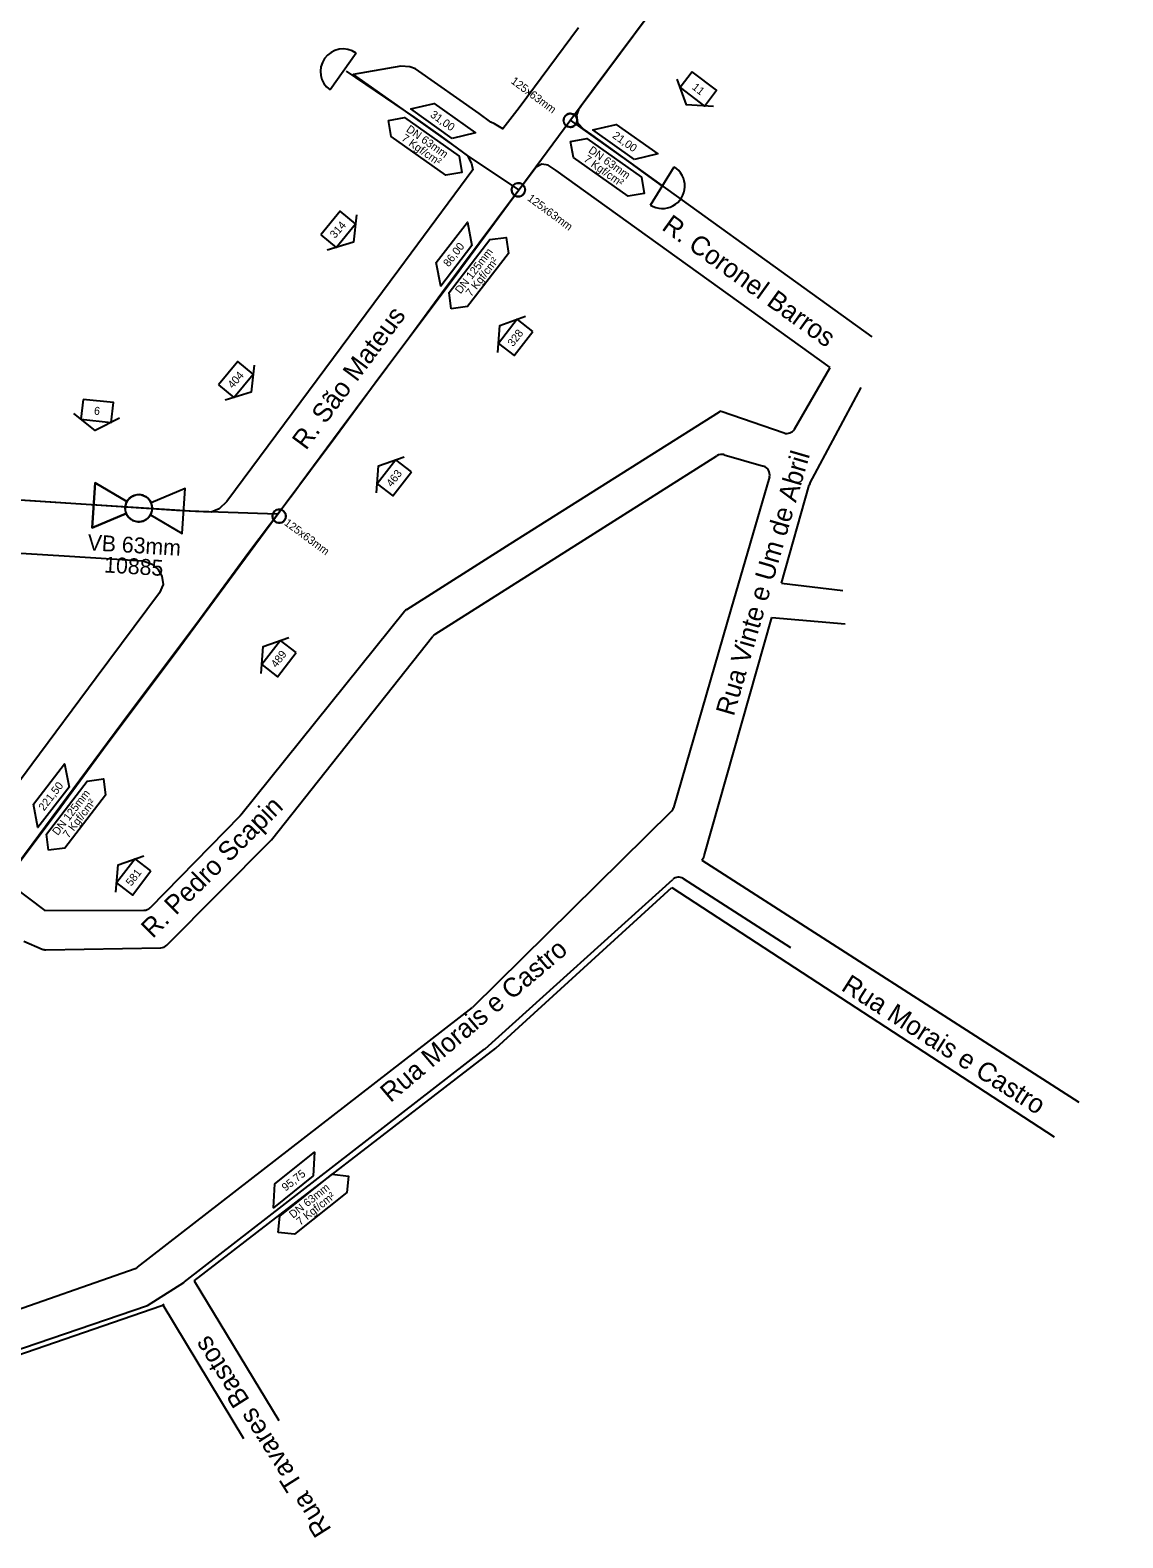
# Model space of a CAD drawing. Extents: x 656692 to 673945, y 7585994 to 7599066.
# Drawn here: x 669719 to 670131, y 7591270 to 7591839 of the extents above; entities that cross this region are included whole.
import ezdxf

# ---------------------------------------------------------------- set-up
doc = ezdxf.new("R2010")
doc.units = 0
for name, color, linetype in [('FORMATO', 7, 'Continuous'), ('LOGRADOURO', 7, 'Continuous'), ('LOGRADOURO_TEXTO', 7, 'Continuous'), ('NUM_REF', 7, 'Continuous'), ('SIMBOLO', 7, 'Continuous'), ('TEXTO', 7, 'Continuous'), ('TUBO_PEAD_GN_125', 7, 'Continuous'), ('TUBO_PEAD_GN_63', 7, 'Continuous'), ('VALVULA_PEAD_63', 7, 'Continuous')]:
    doc.layers.add(name, color=color, linetype=linetype)

# ---------------------------------------------------------------- blocks, each defined once
blk = doc.blocks.new('INTERLIGACAO_5')
at = {"layer": 'SIMBOLO'}
blk.add_circle((0, 0), 1.28, dxfattribs=at)
for start, end in [(0, 180), (180, 0)]:
    blk.add_arc((0, 0), 1.28, start, end, dxfattribs=at)
blk = doc.blocks.new('VALVULA_PEAD_DN_9')
at = {"layer": 'VALVULA_PEAD_63'}
for points in [[(-1.14, 0.57), (-4.25, 2.13), (-4.25, -2.13), (-1.14, -0.57)], [(-1.14, -0.57), (-4.25, -2.13), (-4.25, 2.13), (-1.14, 0.57)], [(1.14, -0.57), (4.25, -2.13), (4.25, 2.13), (1.14, 0.57)], [(1.14, -0.57), (4.25, -2.13), (4.25, 2.13), (1.14, 0.57)]]:
    blk.add_lwpolyline(points, dxfattribs=at)
blk.add_circle((0, 0), 1.28, dxfattribs=at)
for start, end in [(90, 270), (153.4349, 206.5651), (270, 90), (0, 26.5651), (333.4349, 0)]:
    blk.add_arc((0, 0), 1.28, start, end, dxfattribs=at)
blk = doc.blocks.new('NUM_REF_1')
at = {"layer": 'NUM_REF'}
blk.add_lwpolyline([(-4.3125, 0.9375), (0, 3.75), (4.3125, 0.9375)], dxfattribs=at)
blk.add_lwpolyline([(2.875, -1.875), (2.875, 1.875), (-2.875, 1.875), (-2.875, -1.875)], close=True, dxfattribs=at)

msp = doc.modelspace()

# ---------------------------------------------------------------- linework, layer by layer
at = {"layer": 'LOGRADOURO'}
for p, q in [((670007.21, 7591688), (670020.73, 7591711.24)), ((670013.03, 7591667.48), (670032.45, 7591703.72)), ((669979.51, 7591694.8), (669979.51, 7591694.8)), ((669979.51, 7591694.8), (670003.3, 7591686.55)), ((669871.62, 7591610.57), (669977.98, 7591677.98)), ((669980.65, 7591678.36), (669995.52, 7591674.05)), ((670002.31, 7591629.85), (670012.76, 7591666.82)), ((670002.31, 7591629.85), (670025.52, 7591627.08)), ((669798.36, 7591542.37), (669860.13, 7591619.25)), ((669973.19, 7591526.89), (669998.63, 7591616.86)), ((669998.63, 7591616.86), (670026.36, 7591614.54)), ((669809.94, 7591533), (669870.8, 7591609.83)), ((669960.71, 7591543.64), (669885.72, 7591469.67)), ((669764.11, 7591507.37), (669798.15, 7591542.13)), ((669770.41, 7591493.22), (669809.69, 7591532.72)), ((669972.25, 7591525.36), (670114.52, 7591433.95)), ((669894.6, 7591454.3), (669960.89, 7591514.97)), ((669960.89, 7591514.97), (670105.17, 7591420.91)), ((669724.35, 7591506.29), (669761.77, 7591506.38)), ((669716.49, 7591494.69), (669723.39, 7591491.73)), ((669724.75, 7591491.47), (669768.14, 7591492.25)), ((669759.33, 7591371.64), (669885.72, 7591469.67)), ((669780.71, 7591366.48), (669894.6, 7591454.3)), ((669576.68, 7591307.6), (669758.4, 7591371.13)), ((669780.71, 7591366.48), (669812.72, 7591313.77)), ((669582.7, 7591293.15), (669768.46, 7591357.24)), ((669768.95, 7591357.46), (669799.32, 7591306.97))]:
    msp.add_line(p, q, dxfattribs=at)
for points in [[(670134.64, 7592013.26), (670085.32, 7592003.09), (670076.1, 7592000.43), (670067.33, 7591995.34), (670060.31, 7591988.26), (670059.13, 7591987.1), (670052.98, 7591979.22), (670052.1, 7591978.06), (670024.13, 7591940.47), (669975.42, 7591875.15), (669951.2, 7591842.74), (669926.87, 7591810.12), (669925.76, 7591808.48), (669925.04, 7591806.5), (669925.41, 7591803.62), (669927.72, 7591801.12), (669930.58, 7591799.11), (670036.36, 7591722.83)], [(669732.22, 7591660.05), (669691.63, 7591662.69), (669689.59, 7591662.76), (669658.39, 7591664.55), (669611.03, 7591667.25), (669609.28, 7591667.76), (669608.08, 7591668.73), (669606.72, 7591670.57), (669605.94, 7591672.66), (669605.3, 7591703.26), (669604.55, 7591740.13), (669604.46, 7591742.15), (669604.98, 7591761.74), (669605.59, 7591769.54), (669608.47, 7591789.79), (669613, 7591809.88), (669613.68, 7591812.11), (669616.11, 7591818.23), (669616.74, 7591819.42), (669621.81, 7591827.55), (669639.28, 7591838.38), (669655.23, 7591855.29)], [(669925.78, 7591839.46), (669903.34, 7591809.24), (669897.23, 7591801.4), (669893.98, 7591803.22), (669892.69, 7591803.89), (669888.25, 7591807.15), (669864.29, 7591824.02), (669862.14, 7591824.79), (669858.74, 7591825.01), (669840.65, 7591821.86), (669859.46, 7591808.61), (669879.5, 7591794.4), (669883.85, 7591791.17), (669885.42, 7591788.29), (669885.81, 7591785.82), (669857.88, 7591748.07), (669793.09, 7591660.64), (669790.19, 7591657.93), (669787.07, 7591656.64), (669781.22, 7591656.88), (669777.37, 7591657.13), (669732.22, 7591660.05)], [(670020.73, 7591711.24), (669917.25, 7591785.61), (669914.34, 7591787.62), (669911.92, 7591787.99), (669909.75, 7591786.89), (669903.7, 7591778.88), (669901.95, 7591776.55), (669874.21, 7591739.26), (669860.72, 7591720.96), (669859.46, 7591719.37), (669835.86, 7591687.6), (669820.72, 7591667.17), (669818.94, 7591664.69), (669816.97, 7591662.05), (669801.4, 7591641.37), (669781.34, 7591614.09), (669756, 7591580.23), (669711.62, 7591520.51), (669711.26, 7591519.36), (669711.3, 7591517.55), (669712.49, 7591515.28), (669724.35, 7591506.29)], [(669860.93, 7591619.97), (669899.97, 7591644.65), (669978.98, 7591694.53)], [(669997.75, 7591669.99), (669983.23, 7591619.87), (669961.55, 7591545.06)], [(669678.34, 7591643.5), (669731.61, 7591640.12), (669761.51, 7591638.28), (669764.9, 7591637.05), (669766.98, 7591635.17), (669768.46, 7591632.53), (669769.03, 7591629.3), (669767.66, 7591626.26), (669743.72, 7591594.09), (669719.43, 7591561.36), (669709.96, 7591548.49)]]:
    msp.add_lwpolyline(points, dxfattribs=at)
for centre, radius, start, end in [((669980.74, 7591691.74), 3.3, 111.8505, 122.2669), ((670004.38, 7591689.65), 3.28, 250.8667, 329.8208), ((669979.74, 7591675.21), 3.28, 73.8393, 122.3654), ((669994.6, 7591670.9), 3.28, 343.8393, 73.8393), ((670015.92, 7591665.93), 3.28, 151.8164, 164.2097), ((669862.68, 7591617.2), 3.28, 122.3005, 141.2188), ((669873.38, 7591607.8), 3.28, 122.3654, 141.6146), ((669958.4, 7591545.97), 3.28, 314.6085, 343.8393), ((669795.8, 7591544.43), 3.28, 315.6037, 321.2188), ((669807.37, 7591535.03), 3.28, 315.1612, 321.6146), ((669970.03, 7591527.78), 3.28, 312.4643, 344.2097), ((669761.76, 7591509.67), 3.28, 270.1408, 315.6037), ((669768.08, 7591495.53), 3.28, 271.0382, 315.1612), ((669724.69, 7591494.75), 3.28, 246.7575, 271.0382), ((669757.32, 7591374.23), 3.28, 289.2711, 307.798), ((669767.39, 7591360.35), 3.28, 289.0364, 307.6372)]:
    msp.add_arc(centre, radius, start, end, dxfattribs=at)
at = {"layer": 'SIMBOLO'}
for points in [[(669878.11, 7591797.73), (669862.42, 7591808.84), (669871.22, 7591810.88), (669886.9, 7591799.78)], [(669946.87, 7591789.81), (669931.18, 7591800.92), (669939.97, 7591802.96), (669955.66, 7591791.86)], [(669885.48, 7591757.25), (669873.77, 7591742.02), (669872.07, 7591750.89), (669883.79, 7591766.12)], [(669733.49, 7591552.84), (669721.78, 7591537.61), (669720.08, 7591546.48), (669731.8, 7591561.71)], [(669825.64, 7591406.1), (669810.62, 7591394.11), (669811.1, 7591403.13), (669826.12, 7591415.11)]]:
    msp.add_lwpolyline(points, close=True, dxfattribs=at)
for points in [[(669854, 7591804.54), (669860.1, 7591805.58), (669880.71, 7591790.99), (669881.75, 7591784.89), (669875.65, 7591783.85), (669855.04, 7591798.44), (669854, 7591804.54)], [(669922.76, 7591796.62), (669928.85, 7591797.66), (669949.46, 7591783.07), (669950.51, 7591776.98), (669944.41, 7591775.93), (669923.8, 7591790.52), (669922.76, 7591796.62)], [(669877.73, 7591733.43), (669876.93, 7591739.57), (669892.32, 7591759.58), (669898.45, 7591760.38), (669899.26, 7591754.25), (669883.86, 7591734.23), (669877.73, 7591733.43)], [(669725.74, 7591529.02), (669724.94, 7591535.15), (669740.33, 7591555.17), (669746.47, 7591555.97), (669747.27, 7591549.84), (669731.87, 7591529.82), (669725.74, 7591529.02)], [(669812.41, 7591384.82), (669813.1, 7591390.97), (669832.84, 7591406.72), (669838.98, 7591406.03), (669838.29, 7591399.88), (669818.56, 7591384.13), (669812.41, 7591384.82)]]:
    msp.add_lwpolyline(points, dxfattribs=at)
at = {"layer": 'TUBO_PEAD_GN_125'}
msp.add_lwpolyline([(669715.12, 7591524.92), (669730.39, 7591545.41), (669746.32, 7591567.21), (669758.86, 7591583.81), (669773.54, 7591603.46), (669788.45, 7591623.56), (669815.34, 7591660.03), (669833.97, 7591685.01), (669850.8, 7591707.83), (669879.6, 7591746.22), (669899.26, 7591773), (669932.81, 7591818.29), (669954.72, 7591847.66)], dxfattribs=at)
at = {"layer": 'TUBO_PEAD_GN_63'}
for p, q in [((669841.78, 7591829.93), (669832, 7591816.02)), ((669952.86, 7591772.54), (669961.83, 7591786.99)), ((669890.5, 7591454.12), (669961.27, 7591518.03)), ((669965.24, 7591518.36), (670005.74, 7591492.32)), ((669777.04, 7591366.1), (669890.32, 7591453.96)), ((669763.14, 7591357.21), (669776.8, 7591365.92)), ((669607.71, 7591304.04), (669763.14, 7591357.21))]:
    msp.add_line(p, q, dxfattribs=at)
for points in [[(669838.06, 7591823.17), (669863.83, 7591805.59), (669873.77, 7591798.56), (669883.75, 7591791.23), (669903.05, 7591778.33)], [(669922.65, 7591804.57), (669944.75, 7591788.85), (669950.93, 7591784.39), (669957.35, 7591779.77)], [(669812.04, 7591655.87), (669778.81, 7591657.03), (669774.02, 7591657.34), (669728.51, 7591660.29), (669713.21, 7591661.29), (669697.48, 7591662.3), (669694.18, 7591662.53), (669673.43, 7591663.69), (669610.95, 7591667.27), (669586.06, 7591669.06)]]:
    msp.add_lwpolyline(points, dxfattribs=at)
for centre, radius, start, end in [((669836.89, 7591822.98), 8.51, 54.9005, 234.9005), ((669957.35, 7591779.77), 8.51, 238.201, 58.201), ((669963.47, 7591515.6), 3.28, 57.2607, 132.0895), ((669888.3, 7591456.55), 3.28, 307.7992, 312.0895), ((669775.03, 7591368.69), 3.28, 302.54, 307.7992)]:
    msp.add_arc(centre, radius, start, end, dxfattribs=at)

# ---------------------------------------------------------------- block references
at = {"layer": 'FORMATO'}
for p, xscale, yscale, rotation in [((669970.96, 7591816.42), 1.9999999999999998, 2.0000000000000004, 142.8974184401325), ((669835.01, 7591763.4), 2, 2, -129.5839750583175), ((669901.99, 7591722.6), 2.0000000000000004, 1.9999999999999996, 52.3798521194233), ((669796.45, 7591706.72), 2, 2, -129.5839750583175), ((669744.12, 7591694.9), 1.9999999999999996, 1.9999999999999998, 173.9239519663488), ((669856.22, 7591669.62), 2.0000000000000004, 1.9999999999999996, 52.3798521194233), ((669812.69, 7591601.4), 2.0000000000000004, 1.9999999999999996, 52.3798521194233), ((669757.94, 7591518.95), 2.0000000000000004, 1.9999999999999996, 52.3798521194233)]:
    msp.add_blockref('NUM_REF_1', p, dxfattribs=dict(at, xscale=xscale, yscale=yscale, rotation=rotation))
at = {"layer": 'SIMBOLO'}
for p, xscale, yscale, rotation in [((669922.65, 7591804.57), 1.9999999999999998, 2.0000000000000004, 143.385), ((669903.05, 7591778.33), 1.9999999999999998, 2.0000000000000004, 143.385), ((669812.78, 7591655.15), 2, 2, -36.61500000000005)]:
    msp.add_blockref('INTERLIGACAO_5', p, dxfattribs=dict(at, xscale=xscale, yscale=yscale, rotation=rotation))
at = {"layer": 'VALVULA_PEAD_63', "xscale": 3.9999999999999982, "yscale": 3.9999999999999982, "rotation": -3.526324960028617}
msp.add_blockref('VALVULA_PEAD_DN_9', (669759.78, 7591658.16), dxfattribs=at)

# ---------------------------------------------------------------- texts
for s, height, rotation, p in [('125x63mm', 3, 323.385, (669899.97, 7591818.82)), ('11', 3, 321.3931, (669968.33, 7591816.61)), ('125x63mm', 3, 323.385, (669906.18, 7591774.6)), ('314', 3, 48.9117, (669833.85, 7591759.78)), ('328', 3, 52.3799, (669901.04, 7591718.91)), ('404', 3, 48.9117, (669795.28, 7591703.1)), ('6', 3, 352.4196, (669742.77, 7591693.57)), ('463', 3, 52.3799, (669855.28, 7591665.94)), ('125x63mm', 3, 323.385, (669814.42, 7591652.07)), ('VB 63mm', 6, 356.4737, (669740.37, 7591642.33)), ('10885', 6, 356.4737, (669746.62, 7591633.93)), ('489', 3, 52.3799, (669811.74, 7591597.71)), ('581', 3, 52.3799, (669756.99, 7591515.27))]:
    msp.add_text(s, height=height, rotation=rotation).set_placement(p)
at = {"layer": 'LOGRADOURO_TEXTO'}
for s, rotation, p in [('R. Coronel Barros', 324.2567, (669956.76, 7591763.56)), ('R. São Mateus', 53.3851, (669822.89, 7591679.76)), ('Rua Vinte e Um de Abril', 73.7866, (669984.3, 7591579.35)), ('R. Pedro Scapin', 44.884, (669765.08, 7591495.5)), ('Rua Morais e Castro', 40.2632, (669854.76, 7591433.55)), ('Rua Morais e Castro', 327.48, (670024.46, 7591476.44)), ('Rua Tavares Bastos', 122.2736, (669832.73, 7591272.68))]:
    msp.add_text(s, height=7.2, rotation=rotation, dxfattribs=at).set_placement(p)
at = {"layer": 'TEXTO'}
for s, rotation, p in [('31,00', 324.7099, (669869.52, 7591806.11)), ('7 Kgf/cm²', 324.7099, (669858.65, 7591797.2)), ('DN 63mm', 324.7099, (669860.46, 7591800.57)), ('21,00', 324.7099, (669938.27, 7591798.19)), ('DN 63mm', 324.7099, (669929.22, 7591792.65)), ('7 Kgf/cm²', 324.7099, (669927.41, 7591789.28)), ('86,00', 52.4392, (669876.77, 7591749)), ('DN 125mm', 52.4392, (669881.24, 7591738.81)), ('7 Kgf/cm²', 52.4392, (669885.24, 7591737.79)), ('221,50', 52.4392, (669724.07, 7591543.67)), ('DN 125mm', 52.4392, (669729.25, 7591534.4)), ('7 Kgf/cm²', 52.4392, (669733.25, 7591533.38)), ('95,75', 38.5905, (669815.21, 7591400.17)), ('DN 63mm', 38.5905, (669818.01, 7591389.94)), ('7 Kgf/cm²', 38.5905, (669820.75, 7591387.26))]:
    msp.add_text(s, height=3, rotation=rotation, dxfattribs=at).set_placement(p)

doc.saveas('drawing.dxf')
